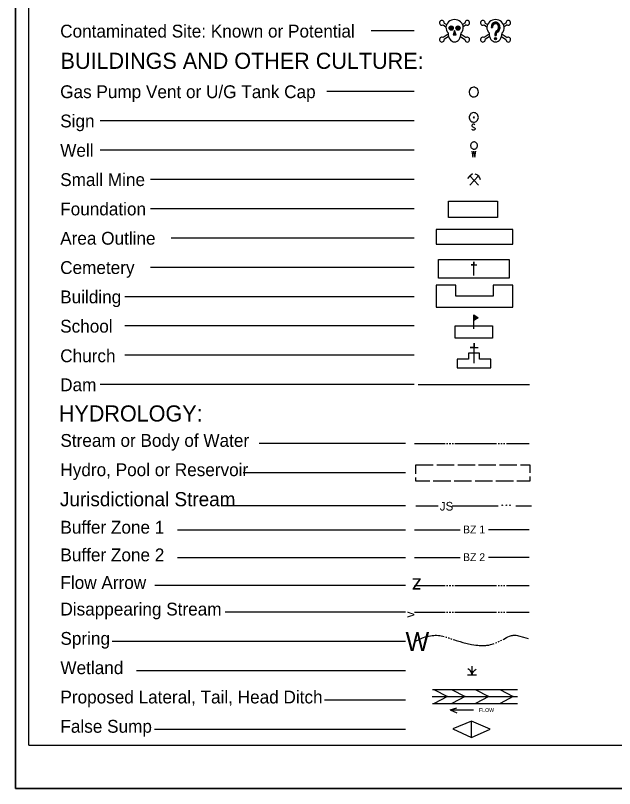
# Model space of a CAD drawing. Extents: x 2025847 to 2026166, y 840763 to 840870.
# Drawn here: x 2026023.88 to 2026059.3, y 840778.42 to 840824.12 of the extents above; entities that cross this region are included whole.
import ezdxf

# ---------------------------------------------------------------- set-up
doc = ezdxf.new("R2010")
doc.units = 0
for name, color, linetype in [('Sheet_Plan', 7, 'Continuous'), ('Sheet_Plot_Border_Outside_CELL', 7, 'Continuous'), ('Sheet_Symbology', 7, 'Continuous'), ('z - Construction', 7, 'Continuous')]:
    doc.layers.add(name, color=color, linetype=linetype)

msp = doc.modelspace()

# ---------------------------------------------------------------- linework, layer by layer
at = {"layer": 'Sheet_Plan'}
for q in [(2026024.668, 840869.009), (2026164.546, 840780.981)]:
    msp.add_line((2026024.668, 840780.981), q, dxfattribs=at)
at = {"layer": 'Sheet_Plot_Border_Outside_CELL'}
msp.add_lwpolyline([(2026023.879, 840870.085), (2026165.546, 840870.085), (2026165.546, 840778.419), (2026023.879, 840778.419)], close=True, dxfattribs=at)
at = {"layer": 'Sheet_Symbology'}
for p, q in [((2026049.157, 840823.561), (2026049.33, 840823.447)), ((2026049.225, 840823.675), (2026049.365, 840823.583)), ((2026050.454, 840823.675), (2026050.314, 840823.583)), ((2026050.522, 840823.561), (2026050.35, 840823.447)), ((2026051.58, 840823.561), (2026051.752, 840823.447)), ((2026051.648, 840823.675), (2026051.788, 840823.583)), ((2026051.998, 840823.421), (2026052.079, 840823.421)), ((2026052.877, 840823.675), (2026052.737, 840823.583)), ((2026052.945, 840823.561), (2026052.772, 840823.447)), ((2026047.446, 840823.211), (2026044.907, 840823.211)), ((2026049.458, 840823.017), (2026049.157, 840822.817)), ((2026049.84, 840823.189), (2026049.84, 840823.189)), ((2026050.221, 840823.017), (2026050.522, 840822.817)), ((2026051.881, 840823.017), (2026051.58, 840822.817)), ((2026052.221, 840823.015), (2026052.221, 840822.94)), ((2026052.233, 840823.015), (2026052.233, 840822.94)), ((2026052.245, 840823.015), (2026052.245, 840822.94)), ((2026052.256, 840823.015), (2026052.256, 840822.94)), ((2026052.262, 840823.233), (2026052.262, 840823.233)), ((2026052.268, 840823.015), (2026052.268, 840822.94)), ((2026052.28, 840823.015), (2026052.28, 840822.94)), ((2026052.291, 840823.015), (2026052.291, 840822.94)), ((2026052.303, 840823.015), (2026052.303, 840822.94)), ((2026052.644, 840823.017), (2026052.945, 840822.817)), ((2026049.487, 840822.876), (2026049.225, 840822.703)), ((2026050.192, 840822.876), (2026050.454, 840822.703)), ((2026051.91, 840822.876), (2026051.648, 840822.703)), ((2026052.221, 840822.94), (2026052.303, 840822.94)), ((2026052.615, 840822.876), (2026052.877, 840822.703)), ((2026047.446, 840819.629), (2026042.294, 840819.629)), ((2026047.446, 840817.896), (2026028.889, 840817.896)), ((2026047.446, 840816.163), (2026028.889, 840816.163)), ((2026047.446, 840814.43), (2026031.853, 840814.43)), ((2026050.748, 840814.634), (2026050.599, 840814.478)), ((2026050.748, 840814.095), (2026051.26, 840814.634)), ((2026051.004, 840814.364), (2026050.975, 840814.395)), ((2026051.004, 840814.364), (2026051.26, 840814.095)), ((2026049.486, 840813.15), (2026052.367, 840813.15)), ((2026049.486, 840812.181), (2026049.486, 840813.15)), ((2026052.367, 840813.15), (2026052.367, 840812.181)), ((2026047.446, 840812.697), (2026031.853, 840812.697)), ((2026052.367, 840812.181), (2026049.486, 840812.181)), ((2026053.279, 840811.466), (2026048.751, 840811.466)), ((2026048.751, 840811.466), (2026048.751, 840810.6)), ((2026053.279, 840810.6), (2026053.279, 840811.466)), ((2026047.446, 840810.964), (2026033.084, 840810.964)), ((2026048.751, 840810.6), (2026053.279, 840810.6)), ((2026048.887, 840809.701), (2026053.074, 840809.701)), ((2026048.887, 840808.592), (2026048.887, 840809.701)), ((2026053.074, 840809.701), (2026053.074, 840808.592)), ((2026047.446, 840809.231), (2026031.853, 840809.231)), ((2026053.074, 840808.592), (2026048.887, 840808.592)), ((2026049.917, 840808.177), (2026048.751, 840808.177)), ((2026048.751, 840808.177), (2026048.751, 840806.877)), ((2026049.917, 840807.527), (2026049.917, 840808.177)), ((2026053.279, 840808.177), (2026052.113, 840808.177)), ((2026052.113, 840808.177), (2026052.113, 840807.527)), ((2026053.279, 840806.877), (2026053.279, 840808.177)), ((2026047.446, 840807.498), (2026030.348, 840807.498)), ((2026052.113, 840807.527), (2026049.917, 840807.527)), ((2026048.751, 840806.877), (2026053.279, 840806.877)), ((2026047.446, 840805.765), (2026030.348, 840805.765)), ((2026049.877, 840805.765), (2026052.077, 840805.765)), ((2026049.877, 840805.046), (2026049.877, 840805.765)), ((2026052.077, 840805.765), (2026052.077, 840805.046)), ((2026052.077, 840805.046), (2026049.877, 840805.046)), ((2026047.446, 840804.032), (2026030.348, 840804.032)), ((2026050.655, 840803.811), (2026049.988, 840803.811)), ((2026049.988, 840803.811), (2026049.988, 840803.283)), ((2026051.322, 840804.161), (2026050.655, 840804.161)), ((2026050.655, 840804.161), (2026050.655, 840803.811)), ((2026051.322, 840803.811), (2026051.322, 840804.161)), ((2026051.989, 840803.811), (2026051.322, 840803.811)), ((2026051.989, 840803.283), (2026051.989, 840803.811)), ((2026049.988, 840803.283), (2026051.989, 840803.283)), ((2026047.446, 840802.299), (2026028.889, 840802.299)), ((2026047.682, 840802.299), (2026054.268, 840802.299)), ((2026046.93, 840798.816), (2026038.287, 840798.816)), ((2026047.466, 840798.816), (2026049.279, 840798.816)), ((2026049.362, 840798.816), (2026049.444, 840798.816)), ((2026049.526, 840798.816), (2026049.609, 840798.816)), ((2026049.691, 840798.816), (2026049.773, 840798.816)), ((2026049.856, 840798.816), (2026052.325, 840798.816)), ((2026052.407, 840798.816), (2026052.49, 840798.816)), ((2026052.572, 840798.816), (2026052.654, 840798.816)), ((2026052.737, 840798.816), (2026052.819, 840798.816)), ((2026052.901, 840798.816), (2026054.258, 840798.816)), ((2026047.554, 840797.566), (2026048.583, 840797.566)), ((2026047.554, 840797.02), (2026047.554, 840797.566)), ((2026048.789, 840797.566), (2026049.818, 840797.566)), ((2026050.023, 840797.566), (2026051.052, 840797.566)), ((2026051.258, 840797.566), (2026052.287, 840797.566)), ((2026052.493, 840797.566), (2026053.522, 840797.566)), ((2026046.93, 840797.083), (2026037.35, 840797.083)), ((2026049.61, 840796.585), (2026048.581, 840796.585)), ((2026050.844, 840796.585), (2026049.816, 840796.585)), ((2026052.079, 840796.585), (2026051.05, 840796.585)), ((2026053.314, 840796.585), (2026052.285, 840796.585)), ((2026046.93, 840795.125), (2026036.097, 840795.125)), ((2026047.466, 840793.723), (2026050.166, 840793.723)), ((2026054.258, 840793.723), (2026051.845, 840793.723)), ((2026046.93, 840793.685), (2026033.451, 840793.685)), ((2026046.93, 840792.05), (2026033.451, 840792.05)), ((2026047.466, 840792.078), (2026050.166, 840792.078)), ((2026054.258, 840792.078), (2026051.845, 840792.078)), ((2026046.93, 840790.415), (2026032.127, 840790.415)), ((2026047.466, 840790.415), (2026049.279, 840790.415)), ((2026049.362, 840790.415), (2026049.444, 840790.415)), ((2026049.526, 840790.415), (2026049.609, 840790.415)), ((2026049.691, 840790.415), (2026049.773, 840790.415)), ((2026049.856, 840790.415), (2026052.325, 840790.415)), ((2026052.407, 840790.415), (2026052.49, 840790.415)), ((2026052.572, 840790.415), (2026052.654, 840790.415)), ((2026052.737, 840790.415), (2026052.819, 840790.415)), ((2026052.901, 840790.415), (2026054.258, 840790.415)), ((2026046.93, 840788.845), (2026036.269, 840788.845)), ((2026047.466, 840788.845), (2026049.279, 840788.845)), ((2026049.362, 840788.845), (2026049.444, 840788.845)), ((2026049.526, 840788.845), (2026049.609, 840788.845)), ((2026049.691, 840788.845), (2026049.773, 840788.845)), ((2026049.856, 840788.845), (2026052.325, 840788.845)), ((2026052.407, 840788.845), (2026052.49, 840788.845)), ((2026052.572, 840788.845), (2026052.654, 840788.845)), ((2026052.737, 840788.845), (2026052.819, 840788.845)), ((2026052.901, 840788.845), (2026054.258, 840788.845)), ((2026046.93, 840787.112), (2026029.605, 840787.112)), ((2026049.608, 840787.281), (2026049.686, 840787.253)), ((2026052.258, 840787.027), (2026052.334, 840787.06)), ((2026052.412, 840787.091), (2026052.487, 840787.125)), ((2026050.871, 840785.144), (2026050.871, 840785.653)), ((2026046.93, 840785.379), (2026031.026, 840785.379)), ((2026050.611, 840785.144), (2026051.136, 840785.144)), ((2026048.534, 840784.274), (2026053.557, 840784.274)), ((2026048.609, 840784.274), (2026049.414, 840783.858)), ((2026049.655, 840784.274), (2026050.461, 840783.858)), ((2026051.05, 840784.274), (2026051.859, 840783.858)), ((2026052.51, 840784.274), (2026053.301, 840783.858)), ((2026048.513, 840783.858), (2026053.557, 840783.858)), ((2026049.414, 840783.858), (2026048.631, 840783.455)), ((2026050.461, 840783.858), (2026049.681, 840783.455)), ((2026051.859, 840783.858), (2026051.079, 840783.455)), ((2026053.301, 840783.858), (2026052.532, 840783.455)), ((2026046.93, 840783.646), (2026042.142, 840783.646)), ((2026048.534, 840783.455), (2026053.557, 840783.455)), ((2026049.584, 840783.065), (2026049.979, 840783.182)), ((2026049.584, 840783.065), (2026050.955, 840783.065)), ((2026049.584, 840783.065), (2026049.979, 840782.896)), ((2026050.844, 840782.399), (2026049.727, 840781.942)), ((2026050.844, 840781.442), (2026050.844, 840782.399)), ((2026051.94, 840781.921), (2026050.844, 840782.399)), ((2026046.93, 840781.913), (2026032.091, 840781.913)), ((2026049.727, 840781.942), (2026050.844, 840781.442)), ((2026050.844, 840781.442), (2026051.94, 840781.921))]:
    msp.add_line(p, q, dxfattribs=at)
for points in [[(2026049.84, 840823.233), (2026049.75, 840822.973), (2026049.93, 840822.973)], [(2026049.84, 840823.189), (2026049.77, 840822.989), (2026049.909, 840822.989)], [(2026049.84, 840823.145), (2026049.791, 840823.004), (2026049.889, 840823.004)], [(2026049.84, 840823.101), (2026049.811, 840823.019), (2026049.868, 840823.019)], [(2026049.84, 840823.057), (2026049.832, 840823.034), (2026049.848, 840823.034)]]:
    msp.add_lwpolyline(points, close=True, dxfattribs=at)
for points in [[(2026051.251, 840819.592), (2026051.237, 840819.661), (2026051.222, 840819.722), (2026051.186, 840819.776), (2026051.134, 840819.822), (2026051.083, 840819.853), (2026051.025, 840819.876), (2026050.959, 840819.876), (2026050.894, 840819.868), (2026050.835, 840819.837), (2026050.784, 840819.799), (2026050.748, 840819.753), (2026050.719, 840819.691), (2026050.704, 840819.622), (2026050.704, 840819.561), (2026050.719, 840819.492), (2026050.748, 840819.431), (2026050.784, 840819.384), (2026050.835, 840819.346), (2026050.894, 840819.315), (2026050.959, 840819.308), (2026051.025, 840819.308), (2026051.083, 840819.331), (2026051.134, 840819.362), (2026051.186, 840819.408), (2026051.222, 840819.461), (2026051.237, 840819.523), (2026051.251, 840819.592)], [(2026051.244, 840818.097), (2026051.238, 840818.153), (2026051.222, 840818.209), (2026051.195, 840818.26), (2026051.158, 840818.3), (2026051.115, 840818.333), (2026051.067, 840818.361), (2026051.019, 840818.373), (2026050.96, 840818.378), (2026050.907, 840818.367), (2026050.859, 840818.35), (2026050.81, 840818.322), (2026050.773, 840818.283), (2026050.741, 840818.232), (2026050.719, 840818.181), (2026050.709, 840818.125), (2026050.709, 840818.069), (2026050.719, 840818.012), (2026050.741, 840817.962), (2026050.773, 840817.911), (2026050.81, 840817.872), (2026050.859, 840817.843), (2026050.907, 840817.827), (2026050.96, 840817.815), (2026051.019, 840817.821), (2026051.067, 840817.832), (2026051.115, 840817.86), (2026051.158, 840817.894), (2026051.195, 840817.934), (2026051.222, 840817.984), (2026051.238, 840818.041), (2026051.244, 840818.097)], [(2026050.987, 840818.131), (2026050.971, 840818.131), (2026050.955, 840818.119), (2026050.944, 840818.102), (2026050.949, 840818.086), (2026050.96, 840818.069), (2026050.976, 840818.063), (2026050.992, 840818.069), (2026051.003, 840818.08), (2026051.008, 840818.102), (2026051.003, 840818.119), (2026050.987, 840818.131)], [(2026051.039, 840817.663), (2026050.987, 840817.688), (2026050.927, 840817.688), (2026050.873, 840817.663), (2026050.85, 840817.619), (2026050.85, 840817.603), (2026050.875, 840817.562), (2026051.026, 840817.48), (2026051.052, 840817.442), (2026051.049, 840817.409), (2026051.026, 840817.366), (2026050.982, 840817.341), (2026050.92, 840817.341), (2026050.891, 840817.352), (2026050.85, 840817.382)], [(2026051.194, 840816.432), (2026051.188, 840816.469), (2026051.181, 840816.507), (2026051.165, 840816.541), (2026051.142, 840816.572), (2026051.116, 840816.599), (2026051.087, 840816.62), (2026051.051, 840816.633), (2026051.016, 840816.643), (2026050.98, 840816.643), (2026050.945, 840816.64), (2026050.909, 840816.626), (2026050.88, 840816.609), (2026050.851, 840816.586), (2026050.825, 840816.558), (2026050.808, 840816.524), (2026050.796, 840816.49), (2026050.789, 840816.452), (2026050.789, 840816.412), (2026050.796, 840816.374), (2026050.808, 840816.34), (2026050.825, 840816.306), (2026050.851, 840816.278), (2026050.88, 840816.255), (2026050.909, 840816.238), (2026050.945, 840816.224), (2026050.98, 840816.22), (2026051.016, 840816.22), (2026051.051, 840816.231), (2026051.087, 840816.244), (2026051.116, 840816.265), (2026051.142, 840816.292), (2026051.165, 840816.323), (2026051.181, 840816.357), (2026051.188, 840816.394), (2026051.194, 840816.432)], [(2026050.858, 840816.098), (2026050.91, 840815.751), (2026050.977, 840816.098), (2026051.044, 840815.751), (2026051.101, 840816.098)], [(2026051.004, 840814.364), (2026050.748, 840814.634), (2026050.892, 840814.786)], [(2026051.364, 840814.412), (2026051.351, 840814.473), (2026051.33, 840814.53), (2026051.302, 840814.582), (2026051.264, 840814.625), (2026051.223, 840814.669), (2026051.173, 840814.699), (2026051.12, 840814.725), (2026051.066, 840814.738)], [(2026050.982, 840808.741), (2026050.982, 840809.553), (2026050.982, 840809.381), (2026050.818, 840809.381), (2026051.146, 840809.381)], [(2026050.98, 840805.603), (2026050.98, 840806.416), (2026051.238, 840806.256), (2026050.98, 840806.096), (2026050.995, 840806.121), (2026050.995, 840806.393), (2026051.208, 840806.253), (2026051.011, 840806.131), (2026051.014, 840806.368), (2026051.184, 840806.253), (2026051.029, 840806.16), (2026051.029, 840806.339), (2026051.156, 840806.253), (2026051.047, 840806.189), (2026051.047, 840806.31), (2026051.129, 840806.256), (2026051.062, 840806.214), (2026051.062, 840806.281), (2026051.105, 840806.256), (2026051.077, 840806.24), (2026051.074, 840806.259), (2026051.084, 840806.256)], [(2026050.988, 840803.576), (2026050.988, 840804.746), (2026050.988, 840804.497), (2026050.752, 840804.497), (2026051.225, 840804.497)], [(2026053.728, 840797.566), (2026054.289, 840797.566), (2026054.289, 840797.074)], [(2026048.375, 840796.585), (2026047.554, 840796.585), (2026047.554, 840796.803)], [(2026054.289, 840796.858), (2026054.289, 840796.585), (2026053.52, 840796.585)], [(2026047.554, 840795.142), (2026048.871, 840795.142)], [(2026049.698, 840795.142), (2026050.852, 840795.142)], [(2026050.852, 840795.142), (2026052.416, 840795.142)], [(2026053.453, 840795.142), (2026054.393, 840795.142)], [(2026047.467, 840787.112), (2026047.701, 840787.215), (2026047.936, 840787.319), (2026047.994, 840787.343), (2026048.098, 840787.381), (2026048.178, 840787.403), (2026048.299, 840787.433), (2026048.42, 840787.455), (2026048.522, 840787.468), (2026048.613, 840787.476), (2026048.692, 840787.478), (2026048.762, 840787.478), (2026048.884, 840787.47), (2026048.976, 840787.461), (2026049.044, 840787.45), (2026049.146, 840787.429), (2026049.216, 840787.412)], [(2026049.296, 840787.389), (2026049.334, 840787.377), (2026049.374, 840787.364)], [(2026049.452, 840787.337), (2026049.486, 840787.325), (2026049.53, 840787.309)], [(2026052.712, 840787.233), (2026052.751, 840787.254), (2026052.913, 840787.343), (2026052.995, 840787.385), (2026053.08, 840787.422), (2026053.145, 840787.444), (2026053.203, 840787.46), (2026053.254, 840787.47), (2026053.3, 840787.478), (2026053.38, 840787.483), (2026053.44, 840787.483), (2026053.484, 840787.48), (2026053.55, 840787.47), (2026053.614, 840787.455), (2026053.907, 840787.371), (2026054.198, 840787.285)], [(2026049.764, 840787.225), (2026049.827, 840787.202), (2026049.942, 840787.166), (2026050.163, 840787.104), (2026050.33, 840787.06), (2026050.58, 840786.999), (2026050.832, 840786.944), (2026050.972, 840786.918), (2026051.096, 840786.899), (2026051.205, 840786.886), (2026051.3, 840786.877), (2026051.384, 840786.873), (2026051.458, 840786.87), (2026051.585, 840786.873), (2026051.681, 840786.879), (2026051.753, 840786.888), (2026051.859, 840786.904), (2026051.964, 840786.928), (2026052.043, 840786.951), (2026052.112, 840786.972), (2026052.181, 840786.998)], [(2026052.563, 840787.159), (2026052.579, 840787.166), (2026052.638, 840787.194)], [(2026050.871, 840785.144), (2026050.859, 840785.205), (2026050.842, 840785.266), (2026050.813, 840785.322), (2026050.776, 840785.375), (2026050.735, 840785.423), (2026050.685, 840785.457), (2026050.632, 840785.488)], [(2026050.871, 840785.144), (2026050.896, 840785.209), (2026050.925, 840785.275), (2026050.962, 840785.335), (2026051.008, 840785.388), (2026051.057, 840785.435), (2026051.111, 840785.479)]]:
    msp.add_lwpolyline(points, dxfattribs=at)
for centre, major_axis, ratio, start_param, end_param in [((2026049.84, 840823.403), (0.512, 0), 0.931594, 5.564242, 10.143721), ((2026052.262, 840823.403), (0.512, 0), 0.931594, 5.564242, 10.143721), ((2026049.089, 840823.685), (0, 0.144), 0.95, 4.640789, 9.944994), ((2026050.59, 840823.685), (0, 0.144), 0.95, 2.621377, 7.925582), ((2026051.512, 840823.685), (0, 0.144), 0.95, 4.640789, 9.944994), ((2026052.262, 840823.421), (0, 0.309), 0.855, 3.567618, 7.853982), ((2026052.262, 840823.421), (0, 0.296), 0.855, 3.567618, 7.853982), ((2026052.262, 840823.421), (0, 0.282), 0.855, 3.567618, 7.853982), ((2026052.262, 840823.421), (0, 0.268), 0.855, 3.567618, 7.853982), ((2026052.262, 840823.421), (0, 0.255), 0.855, 3.567618, 7.853982), ((2026052.262, 840823.421), (0, 0.241), 0.855, 3.567618, 7.853982), ((2026052.262, 840823.421), (0, 0.227), 0.855, 3.567618, 7.853982), ((2026052.262, 840823.421), (0, 0.214), 0.855, 3.567618, 7.853982), ((2026053.013, 840823.685), (0, 0.144), 0.95, 2.621377, 7.925582), ((2026049.84, 840823.095), (0, -0.539), 0.714915, 4.722735, 7.843636), ((2026052.262, 840823.095), (0, -0.539), 0.714915, 4.722735, 7.843636), ((2026052.42, 840823.015), (0, 0.232), 0.855, 0.426026, 1.570796), ((2026052.42, 840823.015), (0, 0.218), 0.855, 0.426026, 1.570796), ((2026052.42, 840823.015), (0, 0.205), 0.855, 0.426026, 1.570796), ((2026052.42, 840823.015), (0, 0.191), 0.855, 0.426026, 1.570796), ((2026052.42, 840823.015), (0, 0.177), 0.855, 0.426026, 1.570796), ((2026052.42, 840823.015), (0, 0.164), 0.855, 0.426026, 1.570796), ((2026052.42, 840823.015), (0, 0.15), 0.855, 0.426026, 1.570796), ((2026052.42, 840823.015), (0, 0.136), 0.855, 0.426026, 1.570796), ((2026049.089, 840822.692), (0, 0.144), 0.95, 5.762969, 11.067174), ((2026050.59, 840822.692), (0, 0.144), 0.95, 1.499196, 6.803401), ((2026051.512, 840822.692), (0, 0.144), 0.95, 5.762969, 11.067174), ((2026053.013, 840822.692), (0, 0.144), 0.95, 1.499196, 6.803401)]:
    msp.add_ellipse(centre, major_axis=major_axis, ratio=ratio, start_param=start_param, end_param=end_param, dxfattribs=at)
for centre, major_axis, ratio in [((2026049.641, 840823.381), (0, 0.129), 0.95), ((2026049.641, 840823.381), (0, 0.113), 0.95), ((2026049.641, 840823.381), (0, 0.0983), 0.95), ((2026049.641, 840823.381), (0, 0.0831), 0.95), ((2026049.641, 840823.381), (0, 0.0679), 0.95), ((2026049.641, 840823.381), (0, 0.0528), 0.95), ((2026049.641, 840823.381), (0, 0.0376), 0.95), ((2026050.038, 840823.381), (0, 0.129), 0.95), ((2026050.038, 840823.381), (0, 0.113), 0.95), ((2026050.038, 840823.381), (0, 0.0983), 0.95), ((2026050.038, 840823.381), (0, 0.0831), 0.95), ((2026050.038, 840823.381), (0, 0.0679), 0.95), ((2026050.038, 840823.381), (0, 0.0528), 0.95), ((2026050.038, 840823.381), (0, 0.0376), 0.95), ((2026049.641, 840823.381), (0, 0.0224), 0.95), ((2026049.641, 840823.381), (0, 0.00727), 0.95), ((2026050.038, 840823.381), (0, 0.0224), 0.95), ((2026050.038, 840823.381), (0, 0.00727), 0.95), ((2026052.265, 840822.753), (0, 0.0614), 0.95), ((2026052.265, 840822.753), (0, 0.0478), 0.95), ((2026052.265, 840822.753), (0, 0.0338), 0.95), ((2026052.265, 840822.753), (0, 0.0202), 0.95), ((2026052.265, 840822.753), (0, 0.00655), 0.95), ((2026052.658, 840795.166), (0, 0.0171), 0.891571), ((2026052.901, 840795.166), (0, 0.0171), 0.891571), ((2026053.114, 840795.166), (0, 0.0171), 0.891571)]:
    msp.add_ellipse(centre, major_axis=major_axis, ratio=ratio, dxfattribs=at)
at = {"layer": 'z - Construction'}
for p, q in [((2026023.879, 840870.085), (2026023.879, 840778.419)), ((2026023.879, 840778.419), (2026165.546, 840778.419))]:
    msp.add_line(p, q, dxfattribs=at)

# ---------------------------------------------------------------- texts
at = {"layer": 'Sheet_Symbology'}
for s, height, p in [('Contaminated Site: Known or Potential', 0.75818, (2026026.524, 840822.819)), ('BUILDINGS AND OTHER CULTURE:', 0.95314, (2026026.547, 840820.967)), ('Gas Pump Vent or U/G Tank Cap', 0.75818, (2026026.524, 840819.236)), ('Sign', 0.7582, (2026026.525, 840817.505)), ('Well', 0.7582, (2026026.525, 840815.772)), ('Small Mine', 0.7582, (2026026.525, 840814.038)), ('Foundation', 0.7582, (2026026.525, 840812.305)), ('Area Outline', 0.75818, (2026026.525, 840810.572)), ('Cemetery', 0.7582, (2026026.524, 840808.84)), ('Building', 0.7582, (2026026.525, 840807.107)), ('School', 0.7582, (2026026.524, 840805.374)), ('Church', 0.7582, (2026026.526, 840803.624)), ('Dam', 0.7582, (2026026.525, 840801.908)), ('HYDROLOGY:', 0.9531, (2026026.444, 840800.118)), ('Stream or Body of Water', 0.75818, (2026026.537, 840798.62)), ('Hydro, Pool or Reservoir', 0.75818, (2026026.537, 840796.887)), ('Jurisdictional Stream', 0.83582, (2026026.51, 840795.108)), ('JS', 0.5117, (2026048.963, 840794.854)), ('Buffer Zone 1', 0.75818, (2026026.537, 840793.489)), ('BZ 1', 0.4605, (2026050.343, 840793.505)), ('Buffer Zone 2', 0.75818, (2026026.537, 840791.854)), ('BZ 2', 0.4605, (2026050.343, 840791.867)), ('Flow Arrow', 0.7582, (2026026.537, 840790.219)), ('Disappearing Stream', 0.75818, (2026026.537, 840788.649)), ('Spring', 0.7582, (2026026.537, 840786.916)), ('W', 1.105, (2026046.943, 840786.56)), ('Wetland', 0.7582, (2026026.537, 840785.183)), ('Proposed Lateral, Tail, Head Ditch', 0.75818, (2026026.537, 840783.45)), ('FLOW', 0.2247, (2026051.279, 840782.948)), ('False Sump', 0.7582, (2026026.537, 840781.717))]:
    msp.add_text(s, height=height, dxfattribs=at).set_placement(p)
for s, height, rotation, p in [('z', 0.866, 180, (2026047.879, 840790.848)), ('v', 0.543, 89.7712, (2026047.466, 840788.521))]:
    msp.add_text(s, height=height, rotation=rotation, dxfattribs=at).set_placement(p)

doc.saveas('drawing.dxf')
